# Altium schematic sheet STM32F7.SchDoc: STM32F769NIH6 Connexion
size A3; Date: 29-OCT-2015; Author: A.B; CompanyName: STMicroelectronics; Organization: MCD/TOOLS/GNB; Address1: 12, Rue Jules HOROWITZ; Address2: 38019 Grenoble; Address3: FRANCE; DocumentNumber: MB1225; Revision: B-01; SheetNumber: 3; SheetTotal: 12; Project: STM32F769I-DISCO
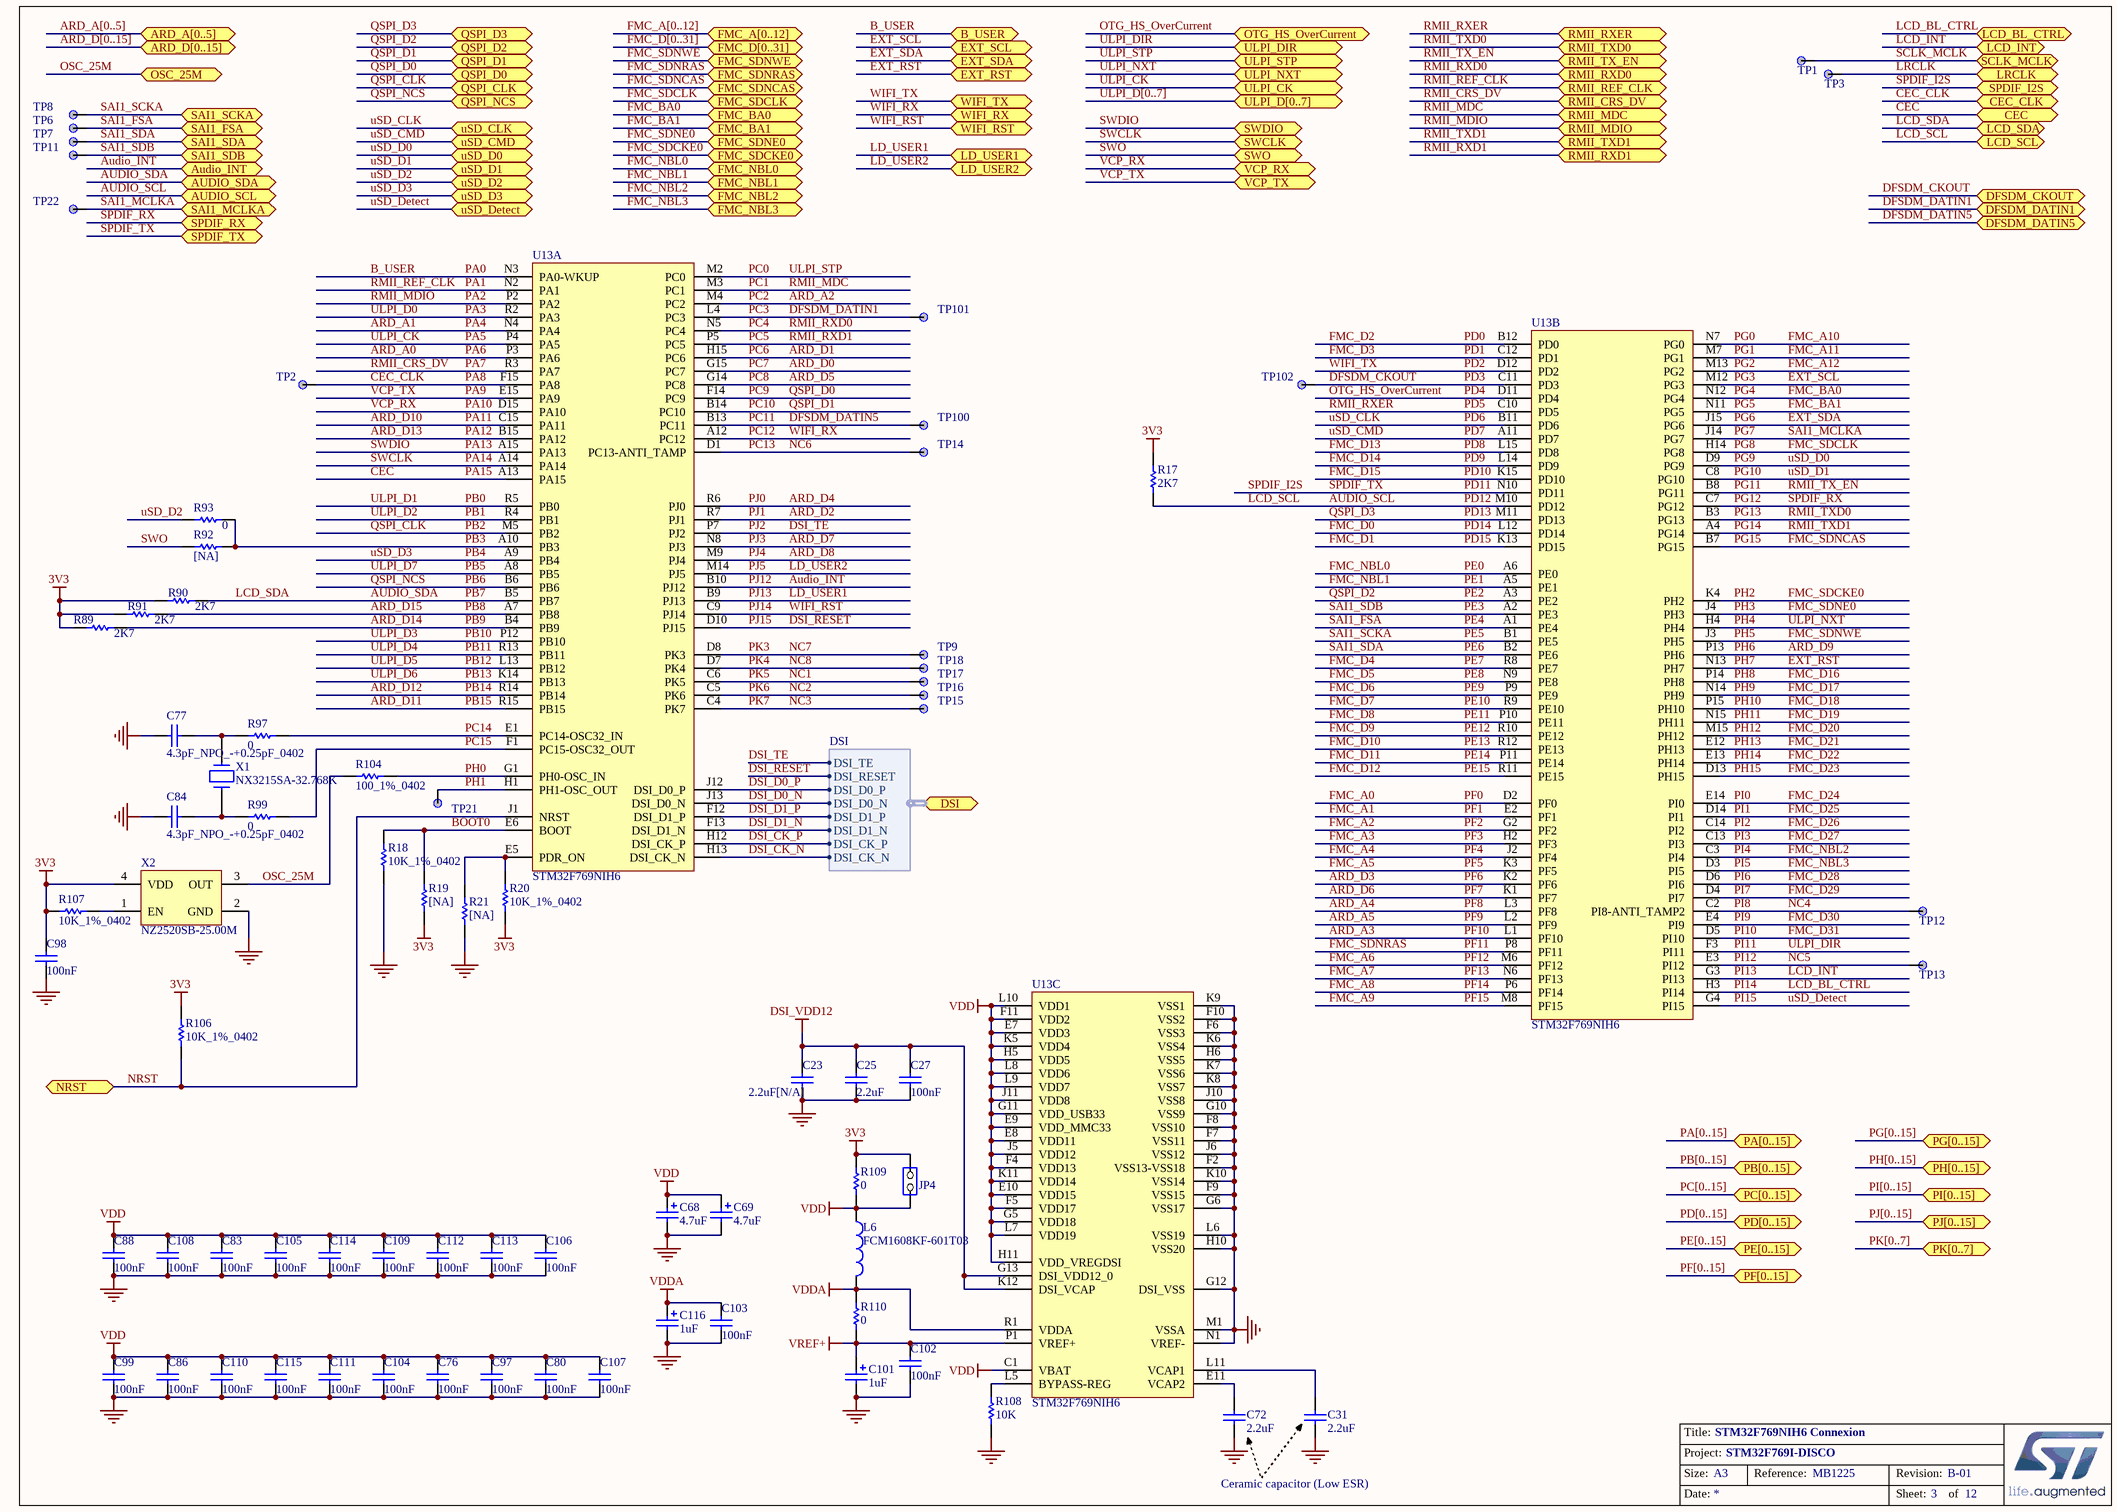
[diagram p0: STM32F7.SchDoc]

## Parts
C23  2.2uF[N/A]  [1206C]
C25  2.2uF  [0603C]
C27  100nF  [0402C]
C31  2.2uF  [1206C]
C68  4.7uF  [TAN-A]
C69  4.7uF  [TAN-A]
C72  2.2uF  [1206C]
C76  100nF  [0402C]
C77  4.3pF_NPO_-+0.25pF_0402  [0402C]
C80  100nF  [0402C]
C83  100nF  [0402C]
C84  4.3pF_NPO_-+0.25pF_0402  [0402C]
C86  100nF  [0402C]
C88  100nF  [0402C]
C97  100nF  [0402C]
C98  100nF  [0402C]
C99  100nF  [0402C]
C101  1uF  [TAN-A]
C102  100nF  [0402C]
C103  100nF  [0402C]
C104  100nF  [0402C]
C105  100nF  [0402C]
C106  100nF  [0402C]
C107  100nF  [0402C]
C108  100nF  [0402C]
C109  100nF  [0402C]
C110  100nF  [0402C]
C111  100nF  [0402C]
C112  100nF  [0402C]
C113  100nF  [0402C]
C114  100nF  [0402C]
C115  100nF  [0402C]
C116  1uF  [TAN-A]
JP4  JP2  [SIP2]  (value not drawn)
L6  FCM1608KF-601T03  [0603L]
R17  2K7  [0402R]
R18  10K_1%_0402  [0402R]
R19  [NA]  [0402R]
R20  10K_1%_0402  [0402R]
R21  [NA]  [0402R]
R89  2K7  [0402R]
R90  2K7  [0402R]
R91  2K7  [0402R]
R92  [NA]  [0402R]
R93  0  [0402R]
R97  0  [0402R]
R99  0  [0402R]
R104  100_1%_0402  [0402R]
R106  10K_1%_0402  [0402R]
R107  10K_1%_0402  [0402R]
R108  10K  [0402R]
R109  0  [0603R-GS]
R110  0  [0603R-GS]
TP1  TP  [TP_C40]  (value not drawn)
TP2  TP  [TP_C40]  (value not drawn)
TP3  TP  [TP_C40]  (value not drawn)
TP6  TP  [TP_C40]  (value not drawn)
TP7  TP  [TP_C40]  (value not drawn)
TP8  TP  [TP_C40]  (value not drawn)
TP9  TP  [TP_C40]  (value not drawn)
TP11  TP  [TP_C40]  (value not drawn)
TP12  TP  [TP_C40]  (value not drawn)
TP13  TP  [TP_C40]  (value not drawn)
TP14  TP  [TP_C40]  (value not drawn)
TP15  TP  [TP_C40]  (value not drawn)
TP16  TP  [TP_C40]  (value not drawn)
TP17  TP  [TP_C40]  (value not drawn)
TP18  TP  [TP_C40]  (value not drawn)
TP21  TP  [TP_C40]  (value not drawn)
TP22  TP  [TP_C40]  (value not drawn)
TP100  TP  [TP_C40]  (value not drawn)
TP101  TP  [TP_C40]  (value not drawn)
TP102  TP  [TP_C40]  (value not drawn)
U13  STM32F769NIH6  [BGA216_0R8_13X13]  (parts A,B,C of 3)
X1  NX3215SA-32.768K  [XTAL_2SM_3R2X1R5]
X2  NZ2520SB-25.00M  [OSC_4SM_2R5X2]

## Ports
ARD_A[0..5], ARD_D[0..15], Audio_INT, AUDIO_SCL, AUDIO_SDA, B_USER, CEC, CEC_CLK, DFSDM_CKOUT, DFSDM_DATIN1, DFSDM_DATIN5, DSI (harness DSI), EXT_RST, EXT_SCL, EXT_SDA, FMC_A[0..12], FMC_BA0, FMC_BA1, FMC_D[0..31], FMC_NBL0, FMC_NBL1, FMC_NBL2, FMC_NBL3, FMC_SDCKE0, FMC_SDCLK, FMC_SDNCAS, FMC_SDNE0, FMC_SDNRAS, FMC_SDNWE, LCD_BL_CTRL, LCD_INT, LCD_SCL, LCD_SDA, LD_USER1, LD_USER2, LRCLK, NRST, OSC_25M, OTG_HS_OverCurrent, PA[0..15], PB[0..15], PC[0..15], PD[0..15], PE[0..15], PF[0..15], PG[0..15], PH[0..15], PI[0..15], PJ[0..15], PK[0..7], QSPI_CLK, QSPI_D0, QSPI_D1, QSPI_D2, QSPI_D3, QSPI_NCS, RMII_CRS_DV, RMII_MDC, RMII_MDIO, RMII_REF_CLK, RMII_RXD0, RMII_RXD1, RMII_RXER, RMII_TX_EN, RMII_TXD0, RMII_TXD1, SAI1_FSA, SAI1_MCLKA, SAI1_SCKA, SAI1_SDA, SAI1_SDB, SCLK_MCLK, SPDIF_I2S, SPDIF_RX, SPDIF_TX, SWCLK, SWDIO, SWO, ULPI_CK, ULPI_D[0..7], ULPI_DIR, ULPI_NXT, ULPI_STP, uSD_CLK, uSD_CMD, uSD_D0, uSD_D1, uSD_D2, uSD_D3, uSD_Detect, VCP_RX, VCP_TX, WIFI_RST, WIFI_RX, WIFI_TX

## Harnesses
DSI: DSI_CK_P, DSI_CK_N, DSI_D0_P, DSI_D0_N, DSI_D1_P, DSI_D1_N, DSI_TE, DSI_RESET

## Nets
3V3: C98.2 JP4.2(NO) R17.2 R19.1 R20.1 R89.1 R90.1 R91.1 R106.2 R107.1 R109.2 X2.4(VDD)
DSI_VDD12: C23.2 C25.2 C27.2 U13.G13(DSI_VDD12_0) U13.K12(DSI_VCAP)
GND: C23.1 C25.1 C27.1 C31.1 C68.2 C69.2 C72.1 C76.1 C77.1 C80.1 C83.1 C84.1 C86.1 C88.1 C97.1 C98.1 C99.1 C101.2 C102.1 C103.1 C104.1 C105.1 C106.1 C107.1 C108.1 C109.1 C110.1 C111.1 C112.1 C113.1 C114.1 C115.1 C116.2 R18.1 R21.1 R108.1 U13.F2(VSS13-VSS18) U13.F6(VSS3) U13.F7(VSS11) U13.F8(VSS10) U13.F9(VSS15) U13.F10(VSS2) U13.G6(VSS17) U13.G10(VSS9) U13.G12(DSI_VSS) U13.H6(VSS5) U13.H10(VSS20) U13.J6(VSS12) U13.J10(VSS8) U13.K6(VSS4) U13.K7(VSS6) U13.K8(VSS7) U13.K9(VSS1) U13.K10(VSS14) U13.L6(VSS19) U13.M1(VSSA) U13.N1(VREF-) X2.2(GND)
VDD: C68.1 C69.1 C76.2 C80.2 C83.2 C86.2 C88.2 C97.2 C99.2 C104.2 C105.2 C106.2 C107.2 C108.2 C109.2 C110.2 C111.2 C112.2 C113.2 C114.2 C115.2 JP4.1(COMMON) L6.1 R109.1 U13.C1(VBAT) U13.E7(VDD3) U13.E8(VDD11) U13.E9(VDD_MMC33) U13.E10(VDD15) U13.F4(VDD13) U13.F5(VDD17) U13.F11(VDD2) U13.G5(VDD18) U13.G11(VDD_USB33) U13.H5(VDD5) U13.H11(VDD_VREGDSI) U13.J5(VDD12) U13.J11(VDD8) U13.K5(VDD4) U13.K11(VDD14) U13.L7(VDD19) U13.L8(VDD6) U13.L9(VDD7) U13.L10(VDD1)
VDDA: C103.2 C116.1 L6.2 R110.1 U13.R1(VDDA)
VREF+: C101.1 C102.2 R110.2 U13.P1(VREF+)
ARD_A0: U13.P3(PA6)  [also labelled PA6]
ARD_A1: U13.N4(PA4)  [also labelled PA4]
ARD_A2: U13.M4(PC2)  [also labelled PC2]
ARD_A3: U13.L1(PF10)  [also labelled PF10]
ARD_A4: U13.L3(PF8)  [also labelled PF8]
ARD_A5: U13.L2(PF9)  [also labelled PF9]
ARD_D0: U13.G15(PC7)  [also labelled PC7]
ARD_D1: U13.H15(PC6)  [also labelled PC6]
ARD_D2: U13.R7(PJ1)  [also labelled PJ1]
ARD_D3: U13.K2(PF6)  [also labelled PF6]
ARD_D4: U13.R6(PJ0)  [also labelled PJ0]
ARD_D5: U13.G14(PC8)  [also labelled PC8]
ARD_D6: U13.K1(PF7)  [also labelled PF7]
ARD_D7: U13.N8(PJ3)  [also labelled PJ3]
ARD_D8: U13.M9(PJ4)  [also labelled PJ4]
ARD_D9: U13.P13(PH6)  [also labelled PH6]
ARD_D10: U13.C15(PA11)  [also labelled PA11]
ARD_D11: U13.R15(PB15)  [also labelled PB15]
ARD_D12: U13.R14(PB14)  [also labelled PB14]
ARD_D13: U13.B15(PA12)  [also labelled PA12]
ARD_D14: R89.2 U13.B4(PB9)  [also labelled PB9]
ARD_D15: R91.2 U13.A7(PB8)  [also labelled PB8]
Audio_INT: U13.B10(PJ12) ; port Audio_INT  [also labelled PJ12]
AUDIO_SCL: R17.1 U13.M10(PD12) ; port AUDIO_SCL, port LCD_SCL  [also labelled LCD_SCL, PD12]
AUDIO_SDA: R90.2 U13.B5(PB7) ; port AUDIO_SDA, port LCD_SDA  [also labelled LCD_SDA, PB7]
B_USER: U13.N3(PA0-WKUP) ; port B_USER  [also labelled PA0]
BOOT0: R18.2 R19.2 U13.E6(BOOT)
CEC: U13.A13(PA15) ; port CEC  [also labelled PA15]
CEC_CLK: TP2.1 U13.F15(PA8) ; port CEC_CLK  [also labelled PA8]
DFSDM_CKOUT: TP102.1 U13.C11(PD3) ; port DFSDM_CKOUT  [also labelled PD3]
DFSDM_DATIN1: TP101.1 U13.L4(PC3) ; port DFSDM_DATIN1  [also labelled PC3]
DFSDM_DATIN5: TP100.1 U13.B13(PC11) ; port DFSDM_DATIN5  [also labelled PC11]
DSI_CK_N: U13.H13(DSI_CK_N) ; port DSI.DSI_CK_N
DSI_CK_P: U13.H12(DSI_CK_P) ; port DSI.DSI_CK_P
DSI_D0_N: U13.J13(DSI_D0_N) ; port DSI.DSI_D0_N
DSI_D0_P: U13.J12(DSI_D0_P) ; port DSI.DSI_D0_P
DSI_D1_N: U13.F13(DSI_D1_N) ; port DSI.DSI_D1_N
DSI_D1_P: U13.F12(DSI_D1_P) ; port DSI.DSI_D1_P
DSI_RESET: U13.D10(PJ15) ; port DSI.DSI_RESET  [also labelled PJ15]
DSI_TE: U13.P7(PJ2) ; port DSI.DSI_TE  [also labelled PJ2]
EXT_RST: U13.N13(PH7) ; port EXT_RST  [also labelled PH7]
EXT_SCL: U13.M12(PG3) ; port EXT_SCL  [also labelled PG3]
EXT_SDA: U13.J15(PG6) ; port EXT_SDA  [also labelled PG6]
FMC_A0: U13.D2(PF0)  [also labelled PF0]
FMC_A1: U13.E2(PF1)  [also labelled PF1]
FMC_A2: U13.G2(PF2)  [also labelled PF2]
FMC_A3: U13.H2(PF3)  [also labelled PF3]
FMC_A4: U13.J2(PF4)  [also labelled PF4]
FMC_A5: U13.K3(PF5)  [also labelled PF5]
FMC_A6: U13.M6(PF12)  [also labelled PF12]
FMC_A7: U13.N6(PF13)  [also labelled PF13]
FMC_A8: U13.P6(PF14)  [also labelled PF14]
FMC_A9: U13.M8(PF15)  [also labelled PF15]
FMC_A10: U13.N7(PG0)  [also labelled PG0]
FMC_A11: U13.M7(PG1)  [also labelled PG1]
FMC_A12: U13.M13(PG2)  [also labelled PG2]
FMC_BA0: U13.N12(PG4) ; port FMC_BA0  [also labelled PG4]
FMC_BA1: U13.N11(PG5) ; port FMC_BA1  [also labelled PG5]
FMC_D0: U13.L12(PD14)  [also labelled PD14]
FMC_D1: U13.K13(PD15)  [also labelled PD15]
FMC_D2: U13.B12(PD0)  [also labelled PD0]
FMC_D3: U13.C12(PD1)  [also labelled PD1]
FMC_D4: U13.R8(PE7)  [also labelled PE7]
FMC_D5: U13.N9(PE8)  [also labelled PE8]
FMC_D6: U13.P9(PE9)  [also labelled PE9]
FMC_D7: U13.R9(PE10)  [also labelled PE10]
FMC_D8: U13.P10(PE11)  [also labelled PE11]
FMC_D9: U13.R10(PE12)  [also labelled PE12]
FMC_D10: U13.R12(PE13)  [also labelled PE13]
FMC_D11: U13.P11(PE14)  [also labelled PE14]
FMC_D12: U13.R11(PE15)  [also labelled PE15]
FMC_D13: U13.L15(PD8)  [also labelled PD8]
FMC_D14: U13.L14(PD9)  [also labelled PD9]
FMC_D15: U13.K15(PD10)  [also labelled PD10]
FMC_D16: U13.P14(PH8)  [also labelled PH8]
FMC_D17: U13.N14(PH9)  [also labelled PH9]
FMC_D18: U13.P15(PH10)  [also labelled PH10]
FMC_D19: U13.N15(PH11)  [also labelled PH11]
FMC_D20: U13.M15(PH12)  [also labelled PH12]
FMC_D21: U13.E12(PH13)  [also labelled PH13]
FMC_D22: U13.E13(PH14)  [also labelled PH14]
FMC_D23: U13.D13(PH15)  [also labelled PH15]
FMC_D24: U13.E14(PI0)  [also labelled PI0]
FMC_D25: U13.D14(PI1)  [also labelled PI1]
FMC_D26: U13.C14(PI2)  [also labelled PI2]
FMC_D27: U13.C13(PI3)  [also labelled PI3]
FMC_D28: U13.D6(PI6)  [also labelled PI6]
FMC_D29: U13.D4(PI7)  [also labelled PI7]
FMC_D30: U13.E4(PI9)  [also labelled PI9]
FMC_D31: U13.D5(PI10)  [also labelled PI10]
FMC_NBL0: U13.A6(PE0) ; port FMC_NBL0  [also labelled PE0]
FMC_NBL1: U13.A5(PE1) ; port FMC_NBL1  [also labelled PE1]
FMC_NBL2: U13.C3(PI4) ; port FMC_NBL2  [also labelled PI4]
FMC_NBL3: U13.D3(PI5) ; port FMC_NBL3  [also labelled PI5]
FMC_SDCKE0: U13.K4(PH2) ; port FMC_SDCKE0  [also labelled PH2]
FMC_SDCLK: U13.H14(PG8) ; port FMC_SDCLK  [also labelled PG8]
FMC_SDNCAS: U13.B7(PG15) ; port FMC_SDNCAS  [also labelled PG15]
FMC_SDNE0: U13.J4(PH3) ; port FMC_SDNE0  [also labelled PH3]
FMC_SDNRAS: U13.P8(PF11) ; port FMC_SDNRAS  [also labelled PF11]
FMC_SDNWE: U13.J3(PH5) ; port FMC_SDNWE  [also labelled PH5]
LCD_BL_CTRL: U13.H3(PI14) ; port LCD_BL_CTRL  [also labelled PI14]
LCD_INT: U13.G3(PI13) ; port LCD_INT  [also labelled PI13]
LD_USER1: U13.B9(PJ13) ; port LD_USER1  [also labelled PJ13]
LD_USER2: U13.M14(PJ5) ; port LD_USER2  [also labelled PJ5]
LRCLK: TP3.1 ; port LRCLK
NC1: TP17.1 U13.C6(PK5)  [also labelled PK5]
NC2: TP16.1 U13.C5(PK6)  [also labelled PK6]
NC3: TP15.1 U13.C4(PK7)  [also labelled PK7]
NC4: TP12.1 U13.C2(PI8-ANTI_TAMP2)  [also labelled PI8]
NC5: TP13.1 U13.E3(PI12)  [also labelled PI12]
NC6: TP14.1 U13.D1(PC13-ANTI_TAMP)  [also labelled PC13]
NC7: TP9.1 U13.D8(PK3)  [also labelled PK3]
NC8: TP18.1 U13.D7(PK4)  [also labelled PK4]
NRST: R106.1 U13.J1(NRST) ; port NRST
OSC_25M: R104.1 X2.3(OUT) ; port OSC_25M
OTG_HS_OverCurrent: U13.D11(PD4) ; port OTG_HS_OverCurrent  [also labelled PD4]
PA1: U13.N2(PA1) ; port RMII_REF_CLK  [also labelled RMII_REF_CLK]
PA2: U13.P2(PA2) ; port RMII_MDIO  [also labelled RMII_MDIO]
PA3: U13.R2(PA3)  [also labelled ULPI_D0]
PA5: U13.P4(PA5) ; port ULPI_CK  [also labelled ULPI_CK]
PA7: U13.R3(PA7) ; port RMII_CRS_DV  [also labelled RMII_CRS_DV]
PA9: U13.E15(PA9) ; port VCP_TX  [also labelled VCP_TX]
PA10: U13.D15(PA10) ; port VCP_RX  [also labelled VCP_RX]
PA13: U13.A15(PA13) ; port SWDIO  [also labelled SWDIO]
PA14: U13.A14(PA14) ; port SWCLK  [also labelled SWCLK]
PB0: U13.R5(PB0)  [also labelled ULPI_D1]
PB1: U13.R4(PB1)  [also labelled ULPI_D2]
PB2: U13.M5(PB2) ; port QSPI_CLK  [also labelled QSPI_CLK]
PB3: R92.2 R93.2 U13.A10(PB3)
PB4: U13.A9(PB4) ; port uSD_D3  [also labelled uSD_D3]
PB5: U13.A8(PB5)  [also labelled ULPI_D7]
PB6: U13.B6(PB6) ; port QSPI_NCS  [also labelled QSPI_NCS]
PB10: U13.P12(PB10)  [also labelled ULPI_D3]
PB11: U13.R13(PB11)  [also labelled ULPI_D4]
PB12: U13.L13(PB12)  [also labelled ULPI_D5]
PB13: U13.K14(PB13)  [also labelled ULPI_D6]
PC0: U13.M2(PC0) ; port ULPI_STP  [also labelled ULPI_STP]
PC1: U13.M3(PC1) ; port RMII_MDC  [also labelled RMII_MDC]
PC4: U13.N5(PC4) ; port RMII_RXD0  [also labelled RMII_RXD0]
PC5: U13.P5(PC5) ; port RMII_RXD1  [also labelled RMII_RXD1]
PC9: U13.F14(PC9) ; port QSPI_D0  [also labelled QSPI_D0]
PC10: U13.B14(PC10) ; port QSPI_D1  [also labelled QSPI_D1]
PC12: U13.A12(PC12) ; port WIFI_RX  [also labelled WIFI_RX]
PC14: R97.2 U13.E1(PC14-OSC32_IN)
PC15: R99.2 U13.F1(PC15-OSC32_OUT)
PD2: U13.D12(PD2) ; port WIFI_TX  [also labelled WIFI_TX]
PD5: U13.C10(PD5) ; port RMII_RXER  [also labelled RMII_RXER]
PD6: U13.B11(PD6) ; port uSD_CLK  [also labelled uSD_CLK]
PD7: U13.A11(PD7) ; port uSD_CMD  [also labelled uSD_CMD]
PD11: U13.N10(PD11) ; port SPDIF_TX, port SPDIF_I2S  [also labelled SPDIF_I2S, SPDIF_TX]
PD13: U13.M11(PD13) ; port QSPI_D3  [also labelled QSPI_D3]
PE2: U13.A3(PE2) ; port QSPI_D2  [also labelled QSPI_D2]
PE3: TP11.1 U13.A2(PE3) ; port SAI1_SDB  [also labelled SAI1_SDB]
PE4: TP6.1 U13.A1(PE4) ; port SAI1_FSA  [also labelled SAI1_FSA]
PE5: TP8.1 U13.B1(PE5) ; port SAI1_SCKA  [also labelled SAI1_SCKA]
PE6: TP7.1 U13.B2(PE6) ; port SAI1_SDA  [also labelled SAI1_SDA]
PG7: TP22.1 U13.J14(PG7) ; port SAI1_MCLKA  [also labelled SAI1_MCLKA]
PG9: U13.D9(PG9) ; port uSD_D0  [also labelled uSD_D0]
PG10: U13.C8(PG10) ; port uSD_D1  [also labelled uSD_D1]
PG11: U13.B8(PG11) ; port RMII_TX_EN  [also labelled RMII_TX_EN]
PG12: U13.C7(PG12) ; port SPDIF_RX  [also labelled SPDIF_RX]
PG13: U13.B3(PG13) ; port RMII_TXD0  [also labelled RMII_TXD0]
PG14: U13.A4(PG14) ; port RMII_TXD1  [also labelled RMII_TXD1]
PH0: R104.2 U13.G1(PH0-OSC_IN)
PH1: TP21.1 U13.H1(PH1-OSC_OUT)
PH4: U13.H4(PH4) ; port ULPI_NXT  [also labelled ULPI_NXT]
PI11: U13.F3(PI11) ; port ULPI_DIR  [also labelled ULPI_DIR]
PI15: U13.G4(PI15) ; port uSD_Detect  [also labelled uSD_Detect]
PJ14: U13.C9(PJ14) ; port WIFI_RST  [also labelled WIFI_RST]
SCLK_MCLK: TP1.1 ; port SCLK_MCLK
SWO: R92.1 ; port SWO
uSD_D2: R93.1 ; port uSD_D2
NetC31_2: C31.2 U13.L11(VCAP1)
NetC72_2: C72.2 U13.E11(VCAP2)
NetC77_2: C77.2 R97.1 X1.1
NetC84_2: C84.2 R99.1 X1.2
NetR20_2: R20.2 R21.2 U13.E5(PDR_ON)
NetR107_2: R107.2 X2.1(EN)
NetR108_2: R108.2 U13.L5(BYPASS-REG)

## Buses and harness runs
bus ARD_A[0..5] = port ARD_A[0..5]
bus ARD_D[0..15] = port ARD_D[0..15]
bus FMC_A[0..12] = port FMC_A[0..12]
bus FMC_D[0..31] = port FMC_D[0..31]
bus PA[0..15] = port PA[0..15]
bus PB[0..15] = port PB[0..15]
bus PC[0..15] = port PC[0..15]
bus PD[0..15] = port PD[0..15]
bus PE[0..15] = port PE[0..15]
bus PF[0..15] = port PF[0..15]
bus PG[0..15] = port PG[0..15]
bus PH[0..15] = port PH[0..15]
bus PI[0..15] = port PI[0..15]
bus PJ[0..15] = port PJ[0..15]
bus PK[0..7] = port PK[0..7]
bus ULPI_D[0..7] = port ULPI_D[0..7]

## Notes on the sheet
- Ceramic capacitor (Low ESR)

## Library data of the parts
C23 = Cap_2.2uF_X7R_10%_1206: Capacitor,2.2uF,16V, X7R,10%,1206,YAGEO; Manuf_Part_1: CC1206KKX7R7BB225; Manuf_Part_2: C1206C225K4RAC; Manuf_2: KEMET; Fitted: NO
C25 = Cap_2.2uF_X5R_10%_0603: Capacitor,2.2uF,10V, X5R,10%,0603,YAGEO; Manuf_Part_1: CC0603KRX5R6BB225; Manuf_Part_2: C0603C225K8PACTU; Manuf_2: KEMET
C27 C76 C80 C83 C86 C88 C97-C99 C102-C115 = Cap_100nF_X7R_10%_0402: Capacitor,100nF,16V,X7R,10%,0402,YAGEO; Manuf_Part_1: CC0402KRX7R7BB104
C31 C72 = Cap_2.2uF_X7R_10%_1206: Capacitor,2.2uF,16V, X7R,10%,1206,YAGEO; Manuf_Part_1: CC1206KKX7R7BB225; Manuf_Part_2: C1206C225K4RAC; Manuf_2: KEMET
C68 C69 = Cap_4.7uF_POL_10%_TANA: Polarized Capacitor,4.7uF,16V,10%,typeA,AVX; Manuf_Part_1: TAJA475K016R
C77 C84 = Cap_4.3pF_NPO_-+0.25pF_0402: Capacitor, 4.3pF, 16V, NPO, -+0.25pF, 0402, KEMET; Manuf_1: AVX; Manuf_Part_1: C0402C439C4GACTU; Order: C0402C439C4GACTU-ND
C101 C116 = Cap_1uF_POL_10%_TANA: Polarized Capacitor,1uF,16V,10%,typeA,AVX; Manuf_Part_1: TAJA105K016R
JP4 = JP2: Fitted: NO
L6 = BEAD_600R_350MA_0603: Bead,600R,350mA,0603,FCM1608KF-601T03,Tai-tech; Manuf_2: TDK; Manuf_Part_2: MPZ1608S300A; Manuf_Part_3: BLM18PG121SN1D; Manuf_3: MURATA; Value: 100uH; Description_2: Bead,30R,5A,0603,MPZ1608S300A,TDK; Description_3: Bead,120R,2A,0603,BLM18PG121SN1D,MURATA
R17 R89-R91 = Res_2K7_1%_0402: Resistor,2K7,0402,1%,YAGEO; Manuf_Part_1: RC0402FR-072K7L
R18 R20 R106-R108 = Res_10K_1%_0402: Resistor,10K,0402,1%,YAGEO; Manuf_Part_1: RC0402FR-0710KL
R19 R21 R92 = Res_NA_0402: Resistor,[NA],0402; Fitted: NO
R93 R97 R99 = Res_0_5%_0402: Resistor,0,0402,5%,YAGEO; Manuf_Part_1: RC0402JR-070RL; Order: 2363467
R104 = Res_100_1%_0402: Resistor,100,0402,1%,YAGEO; Manuf_Part_1: RC0402FR-07100RL; Value: 100; Order: 9239111
R109 R110 = Res_0_5%_0603: Resistor,0,0603,5%,YAGEO; Manuf_Part_1: RC0603JR-070RL; Order: 2363481
TP1-TP3 TP6-TP9 TP11-TP18 TP21 TP22 TP100-TP102 = TP: Test Point; Description: Test Point CMS
U13 = STM32F769NIH6U: STM32F769NIH6 (STM32F7 Big Birdie) TBGA216; Manuf_1: STM; ECCN_US/EU: 3A991A2/NEC; Ref St: xxxxxxxx; Provided: ST
X1 = XTAL_32K_NX3215SA: Crystal 32.768kHz, 6pF, -+20PPM, R=50K, SMD; Manuf_1: NDK; Manuf_Part_1: NX3215SA 32.768KHz EXS00A-MU00525; Description: Crystal 32.768kHz, 6pF, -+20PPM, NDK only for ST, Type NX3215SA,  NDK Spec EXS00A-MU00525; ECCN_US/EU: EAR99/NEC; Ref St: 9157034; NDK Ref: X3101802; Provided: ST
X2 = OSC_25M_NZ2520SB: Oscillator 25.00Mhz, -+50PPM, 3.3V, Temp -55 to +125°C; Manuf_Part_1: NZ2520SB 25MHz END4869B; Manuf_1: NDK; Manuf_Part_2: KC2520B25.0000C10E00; Manuf_2: AVX Corp/Kyocera Corp; ECCN_US/EU: EAR99/NEC; Ref St: 9157031; Provided: ST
